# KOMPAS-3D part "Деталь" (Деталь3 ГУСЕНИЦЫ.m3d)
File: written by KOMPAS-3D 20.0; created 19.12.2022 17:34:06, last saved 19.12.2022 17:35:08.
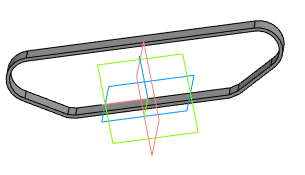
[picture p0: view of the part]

Document properties: Полное имя файла: C:\Users\Семья\Desktop\ДЕТАЛИ ДЛЯ СБОРЩИКА БОРЩЕВИКА\ДЕТАЛИ ДЛЯ ФИНАЛА\Деталь3 ГУСЕНИЦЫ.m3d

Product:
- Part/product: Деталь
    Масса: 0.0558937

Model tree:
1. Эскиз:1
2. Элемент выдавливания:1
     Расстояние 1 = 10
